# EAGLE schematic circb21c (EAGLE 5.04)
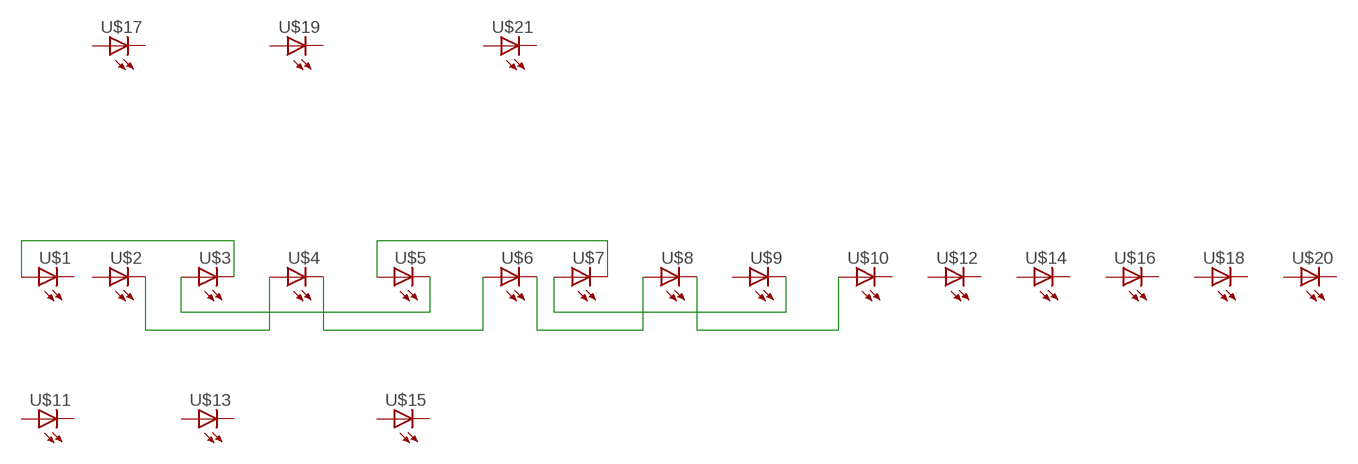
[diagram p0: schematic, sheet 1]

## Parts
U$1  LED5MM  [LED5MM]
U$2  LED5MM  [LED5MM]
U$3  LED5MM  [LED5MM]
U$4  LED5MM  [LED5MM]
U$5  LED5MM  [LED5MM]
U$6  LED5MM  [LED5MM]
U$7  LED5MM  [LED5MM]
U$8  LED5MM  [LED5MM]
U$9  LED5MM  [LED5MM]
U$10  LED5MM  [LED5MM]
U$11  LED5MM  [LED5MM]
U$12  LED5MM  [LED5MM]
U$13  LED5MM  [LED5MM]
U$14  LED5MM  [LED5MM]
U$15  LED5MM  [LED5MM]
U$16  LED5MM  [LED5MM]
U$17  LED5MM  [LED5MM]
U$18  LED5MM  [LED5MM]
U$19  LED5MM  [LED5MM]
U$20  LED5MM  [LED5MM]
U$21  LED5MM  [LED5MM]

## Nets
N$2: U$2.K(C) U$4.A
N$3: U$4.K(C) U$6.A
N$4: U$6.K(C) U$8.A
N$5: U$8.K(C) U$10.A
N$6: U$1.A U$3.K(C)
N$7: U$3.A U$5.K(C)
N$8: U$5.A U$7.K(C)
N$9: U$7.A U$9.K(C)
Unconnected: U$1.K(C) U$2.A U$9.A U$10.K(C) U$11.A U$11.K(C) U$12.A U$12.K(C) U$13.A U$13.K(C) U$14.A U$14.K(C) U$15.A U$15.K(C) U$16.A U$16.K(C) U$17.A U$17.K(C) U$18.A U$18.K(C) U$19.A U$19.K(C) U$20.A U$20.K(C) U$21.A U$21.K(C)

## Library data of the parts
U$1-U$21 = led(2):LED: LED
